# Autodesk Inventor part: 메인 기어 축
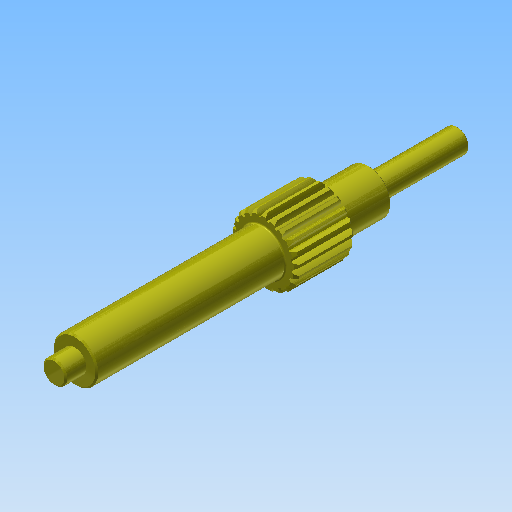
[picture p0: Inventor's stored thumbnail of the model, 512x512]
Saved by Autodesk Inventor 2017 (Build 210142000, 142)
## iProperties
Created: 2018-12
Part Number: 메인 기어 축
Material: 강철, 연강
Document SubType Name: Modeling
Designer: mduedu
Categories: <?xml version="1.0" encoding="UTF-16"?> <MemberInstance><Categories><FamilyTemplate><FamilyTemplateParameter ValueType="xs:double" Id="1" ObjectReferenceKey="da
Density: 7.86 g/cm^3
Appearance: 노란색
Mass: 179.676 g
Surface Area: 75.4119 cm^2
Volume: 22.8595 cm^3
CustomPartVersion: 1
Author: mduedu
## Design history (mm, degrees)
sketch "Sketch1"
  geometry: C1 r 11.3 at (0, 0)
  constraints: 1 centre point
  dimensions: "d0" = 22.6 diameter of C1 (= da_da)
extrude "Extrusion1" new body sketch "Sketch1" distance "d1" = 20 (= da_b); taper "d2" = 0 deg
workplane "Work Plane2"
sketch "Sketch2"
  geometry: C1 r 11.3 at (0, 0) reference; C2 r 10.5 at (0, 0)
  constraints: 1 centre point, 1 coincident
  dimensions: "d3" = 21 diameter of C2 (= da_dw)
feature "피치 지름" sketch "Sketch2" dims "d4" = 10, "d5" = 0
workplane "Work Plane8"
workplane "Work Plane9"
chamfer "모따기1" distance "d49" = 1; stored, may be unused: second distance "d50" = 2, angle "d51" = 45 deg
sketch "스케치3"
  geometry: C1 r 7.5 at (0, 0); 1 further point
  constraints: 1 centre point, 1 coincident
  dimensions: "d52" = 15 diameter of C1
extrude "돌출2" join sketch "스케치3" distance "d53" = 64; taper "d54" = 0 deg
sketch "스케치4"
  geometry: C1 r 4 at (0, 0); 1 further point
  constraints: 1 centre point, 1 coincident
  dimensions: "d55" = 8 diameter of C1
extrude "돌출3" join sketch "스케치4" distance "d56" = 7; taper "d57" = 0 deg
sketch "스케치5"
  geometry: C1 r 7.5 at (0, 0) reference; C2 r 7.5 at (0, 0) reference; 1 further point
extrude "돌출4" join sketch "스케치5" distance "d58" = 16; taper "d59" = 0 deg
sketch "스케치6"
  geometry: C1 r 4 at (0, 0); 1 further point
  constraints: 1 centre point, 1 coincident
  dimensions: "d60" = 8 diameter of C1
extrude "돌출5" join sketch "스케치6" distance "d61" = 30; taper "d62" = 0 deg
chamfer "모따기2" distance "d63" = 0.5; stored, may be unused: second distance "d64" = 2, angle "d65" = 45 deg
fillet "모깎기1" dims "d66" = 0.5
feature "스퍼 기어" dims "da_b" = 20, "da_d" = 21, "da_aw" = 31, "da_da" = 22.6, "da_df" = 19.086, "da_dw" = 21, angle "da_beta" = 0 deg, "da_lefttooth" = 0, "da_righttooth" = 0
sketch "스케치7" dims "d67" = 18
  geometry: C1 r 0.25 at (0, -9); 2 further points
  constraints: 2 vertical alignment, 1 centre point, 1 coincident, 2 other
  dimensions: "d68" = 0.5 diameter of C1
extrude "돌출6" join sketch "스케치7" distance "d69" = 0.3; taper "d70" = 0 deg
body "Solid1"
body "Srf1"
node "투영된 루프1"
other parameters: "d16" = 31 (= da_aw), "d17" = 0, "d34" = 1.496 (computed from da_z), "d39" = 0, "d41" = 0, "d43" = 31 (= da_aw), "d46" = 31 (= da_aw), "d47" = 0, "d48" = 0
